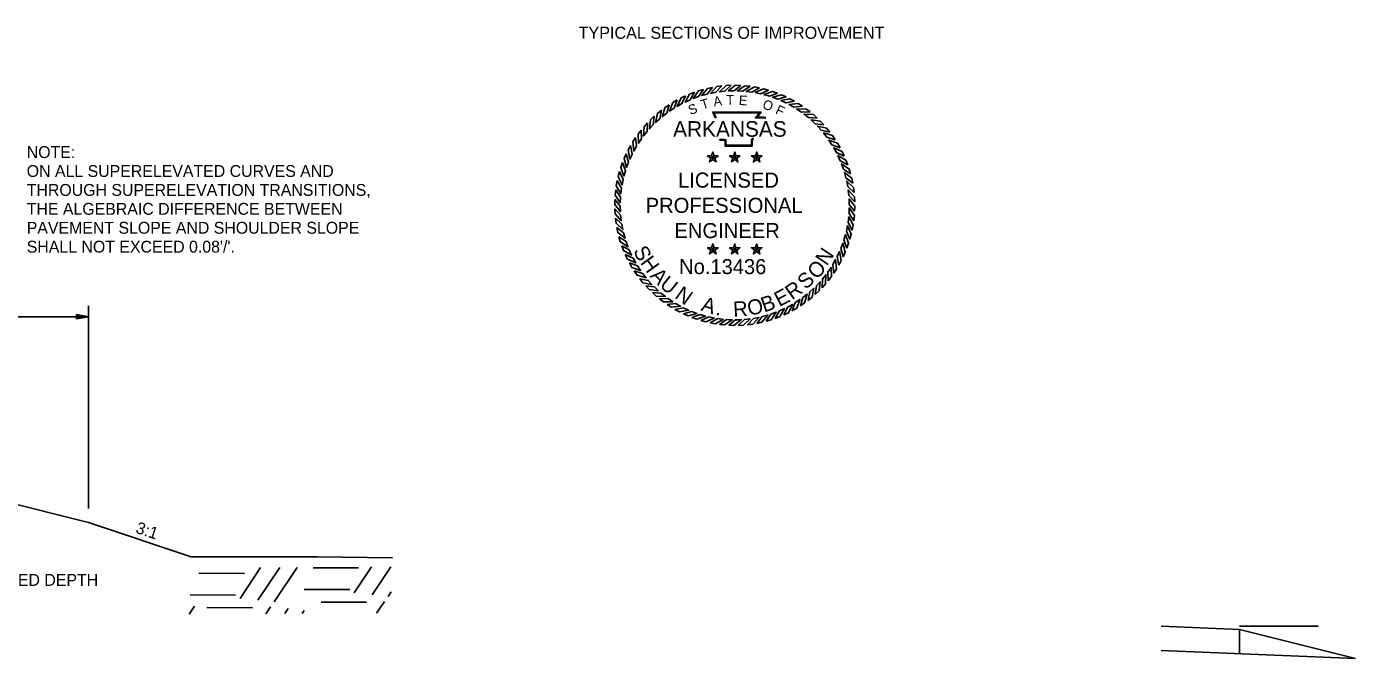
# Model space of a CAD drawing. Extents: x 1398183 to 1398373, y 1967240 to 1968889.
# Drawn here: x 1398293.8 to 1398359.8, y 1967459.6 to 1967491 of the extents above; entities that cross this region are included whole.
import ezdxf

# ---------------------------------------------------------------- set-up
doc = ezdxf.new("R2010")
doc.units = 0
for name, color, linetype in [('1', 7, 'Continuous'), ('10', 7, 'Continuous'), ('19', 7, 'Continuous'), ('42', 7, 'Continuous'), ('9', 7, 'Continuous'), ('G-ANNO-SYMB', 7, 'Continuous')]:
    doc.layers.add(name, color=color, linetype=linetype)

msp = doc.modelspace()

# ---------------------------------------------------------------- linework, layer by layer
at = {"layer": '19'}
for p, q in [((1398296.261, 1967476.707), (1398296.261, 1967476.497)), ((1398296.861, 1967476.602), (1398296.261, 1967476.707)), ((1398296.861, 1967467.07), (1398296.861, 1967477.148)), ((1398296.861, 1967476.602), (1398272.861, 1967476.602)), ((1398296.701, 1967476.617), (1398296.261, 1967476.652)), ((1398296.261, 1967476.497), (1398296.861, 1967476.602)), ((1398296.261, 1967476.547), (1398296.701, 1967476.587)), ((1398280.861, 1967470.374), (1398296.861, 1967466.374)), ((1398296.861, 1967466.374), (1398301.962, 1967464.674)), ((1398350.168, 1967461.218), (1398354.066, 1967461.062)), ((1398354.066, 1967461.062), (1398359.828, 1967459.621)), ((1398354.066, 1967461.062), (1398354.066, 1967459.852)), ((1398354.069, 1967461.218), (1398357.97, 1967461.218)), ((1398350.168, 1967460.008), (1398359.828, 1967459.621))]:
    msp.add_line(p, q, dxfattribs=at)
at = {"layer": '42'}
msp.add_lwpolyline([(1398301.962, 1967464.674), (1398308.248, 1967464.674), (1398311.963, 1967464.624)], dxfattribs=at)
at = {"layer": '9'}
for p, q in [((1398306.369, 1967464.141), (1398305.284, 1967462.514)), ((1398307.229, 1967464.146), (1398306.082, 1967462.426)), ((1398310.927, 1967464.167), (1398310.065, 1967462.875)), ((1398311.879, 1967464.172), (1398310.956, 1967462.787)), ((1398304.609, 1967463.846), (1398302.347, 1967463.852)), ((1398305.416, 1967464.136), (1398304.394, 1967462.602)), ((1398310.281, 1967464.119), (1398308.019, 1967464.125)), ((1398309.842, 1967463.041), (1398307.58, 1967463.046)), ((1398311.907, 1967462.93), (1398311.754, 1967462.699)), ((1398302.134, 1967462.218), (1398301.87, 1967461.822)), ((1398304.17, 1967462.768), (1398301.908, 1967462.774)), ((1398305.898, 1967462.184), (1398305.671, 1967461.843)), ((1398310.68, 1967462.415), (1398308.418, 1967462.42)), ((1398311.57, 1967462.457), (1398311.181, 1967461.874)), ((1398305.008, 1967462.142), (1398302.746, 1967462.148)), ((1398306.788, 1967462.096), (1398306.623, 1967461.849)), ((1398307.586, 1967462.008), (1398307.483, 1967461.853))]:
    msp.add_line(p, q, dxfattribs=at)
at = {"layer": 'G-ANNO-SYMB'}
for points in [[(1398327.879, 1967487.997), (1398327.628, 1967487.944), (1398327.343, 1967487.586), (1398327.61, 1967487.66)], [(1398328.342, 1967488.065), (1398328.088, 1967488.032), (1398327.776, 1967487.698), (1398328.048, 1967487.75)], [(1398328.81, 1967488.097), (1398328.553, 1967488.084), (1398328.216, 1967487.775), (1398328.492, 1967487.806)], [(1398329.278, 1967488.092), (1398329.021, 1967488.099), (1398328.661, 1967487.818), (1398328.938, 1967487.827)], [(1398329.745, 1967488.05), (1398329.489, 1967488.078), (1398329.108, 1967487.825), (1398329.385, 1967487.812)], [(1398330.206, 1967487.972), (1398329.954, 1967488.019), (1398329.554, 1967487.798), (1398329.829, 1967487.763)], [(1398330.661, 1967487.858), (1398330.413, 1967487.925), (1398329.997, 1967487.735), (1398330.268, 1967487.679)], [(1398326.121, 1967487.37), (1398325.898, 1967487.242), (1398325.738, 1967486.814), (1398325.97, 1967486.966)], [(1398326.54, 1967487.578), (1398326.309, 1967487.468), (1398326.115, 1967487.053), (1398326.358, 1967487.187)], [(1398326.975, 1967487.752), (1398326.735, 1967487.661), (1398326.51, 1967487.263), (1398326.763, 1967487.377)], [(1398327.422, 1967487.892), (1398327.176, 1967487.82), (1398326.92, 1967487.441), (1398327.181, 1967487.535)], [(1398331.105, 1967487.708), (1398330.863, 1967487.795), (1398330.433, 1967487.638), (1398330.699, 1967487.561)], [(1398331.535, 1967487.524), (1398331.301, 1967487.629), (1398330.861, 1967487.507), (1398331.12, 1967487.409)], [(1398331.951, 1967487.307), (1398331.725, 1967487.43), (1398331.277, 1967487.343), (1398331.527, 1967487.225)], [(1398325.337, 1967486.858), (1398325.137, 1967486.697), (1398325.046, 1967486.249), (1398325.251, 1967486.435)], [(1398325.719, 1967487.129), (1398325.507, 1967486.984), (1398325.381, 1967486.545), (1398325.6, 1967486.715)], [(1398332.347, 1967487.058), (1398332.132, 1967487.199), (1398331.678, 1967487.147), (1398331.919, 1967487.01)], [(1398332.723, 1967486.779), (1398332.52, 1967486.936), (1398332.063, 1967486.92), (1398332.292, 1967486.764)], [(1398333.076, 1967486.471), (1398332.886, 1967486.643), (1398332.429, 1967486.663), (1398332.646, 1967486.49)], [(1398324.643, 1967486.23), (1398324.471, 1967486.04), (1398324.451, 1967485.583), (1398324.624, 1967485.799)], [(1398324.977, 1967486.557), (1398324.791, 1967486.381), (1398324.735, 1967485.927), (1398324.925, 1967486.13)], [(1398333.404, 1967486.136), (1398333.228, 1967486.323), (1398332.774, 1967486.378), (1398332.976, 1967486.189)], [(1398333.704, 1967485.777), (1398333.543, 1967485.976), (1398333.095, 1967486.068), (1398333.282, 1967485.863)], [(1398324.055, 1967485.501), (1398323.915, 1967485.286), (1398323.967, 1967484.832), (1398324.104, 1967485.072)], [(1398324.335, 1967485.877), (1398324.178, 1967485.674), (1398324.194, 1967485.217), (1398324.35, 1967485.446)], [(1398333.976, 1967485.395), (1398333.831, 1967485.607), (1398333.391, 1967485.733), (1398333.561, 1967485.514)], [(1398334.216, 1967484.993), (1398334.088, 1967485.215), (1398333.66, 1967485.375), (1398333.812, 1967485.144)], [(1398323.589, 1967484.689), (1398323.484, 1967484.455), (1398323.606, 1967484.014), (1398323.704, 1967484.274)], [(1398323.806, 1967485.104), (1398323.683, 1967484.879), (1398323.771, 1967484.43), (1398323.888, 1967484.681)], [(1398327.889, 1967484.509), (1398327.95, 1967484.593), (1398327.889, 1967484.782), (1398327.828, 1967484.593)], [(1398328.98, 1967484.509), (1398329.041, 1967484.593), (1398328.98, 1967484.782), (1398328.919, 1967484.593)], [(1398330.071, 1967484.509), (1398330.132, 1967484.593), (1398330.071, 1967484.782), (1398330.01, 1967484.593)], [(1398334.424, 1967484.573), (1398334.314, 1967484.805), (1398333.9, 1967484.998), (1398334.034, 1967484.755)], [(1398323.405, 1967484.258), (1398323.319, 1967484.016), (1398323.475, 1967483.587), (1398323.553, 1967483.853)], [(1398327.889, 1967484.509), (1398327.828, 1967484.593), (1398327.63, 1967484.593), (1398327.79, 1967484.477)], [(1398327.889, 1967484.509), (1398327.79, 1967484.477), (1398327.729, 1967484.289), (1398327.889, 1967484.405)], [(1398327.889, 1967484.509), (1398327.988, 1967484.477), (1398328.148, 1967484.593), (1398327.95, 1967484.593)], [(1398327.889, 1967484.509), (1398327.889, 1967484.405), (1398328.049, 1967484.289), (1398327.988, 1967484.477)], [(1398328.98, 1967484.509), (1398328.919, 1967484.593), (1398328.721, 1967484.593), (1398328.881, 1967484.477)], [(1398328.98, 1967484.509), (1398328.881, 1967484.477), (1398328.82, 1967484.289), (1398328.98, 1967484.405)], [(1398328.98, 1967484.509), (1398329.079, 1967484.477), (1398329.239, 1967484.593), (1398329.041, 1967484.593)], [(1398328.98, 1967484.509), (1398328.98, 1967484.405), (1398329.14, 1967484.289), (1398329.079, 1967484.477)], [(1398330.071, 1967484.509), (1398330.01, 1967484.593), (1398329.812, 1967484.593), (1398329.972, 1967484.477)], [(1398330.071, 1967484.509), (1398329.972, 1967484.477), (1398329.911, 1967484.289), (1398330.071, 1967484.405)], [(1398330.071, 1967484.509), (1398330.17, 1967484.477), (1398330.33, 1967484.593), (1398330.132, 1967484.593)], [(1398330.071, 1967484.509), (1398330.071, 1967484.405), (1398330.231, 1967484.289), (1398330.17, 1967484.477)], [(1398334.599, 1967484.139), (1398334.508, 1967484.378), (1398334.11, 1967484.603), (1398334.224, 1967484.351)], [(1398334.739, 1967483.691), (1398334.667, 1967483.938), (1398334.288, 1967484.193), (1398334.382, 1967483.933)], [(1398323.141, 1967483.36), (1398323.094, 1967483.108), (1398323.316, 1967482.708), (1398323.35, 1967482.983)], [(1398323.256, 1967483.814), (1398323.189, 1967483.567), (1398323.378, 1967483.15), (1398323.434, 1967483.422)], [(1398334.843, 1967483.235), (1398334.791, 1967483.486), (1398334.433, 1967483.771), (1398334.506, 1967483.503)], [(1398334.912, 1967482.771), (1398334.879, 1967483.026), (1398334.544, 1967483.338), (1398334.596, 1967483.065)], [(1398323.063, 1967482.898), (1398323.036, 1967482.643), (1398323.288, 1967482.262), (1398323.301, 1967482.538)], [(1398334.944, 1967482.304), (1398334.931, 1967482.56), (1398334.622, 1967482.897), (1398334.652, 1967482.622)], [(1398323.022, 1967482.431), (1398323.014, 1967482.175), (1398323.296, 1967481.815), (1398323.287, 1967482.092)], [(1398334.897, 1967481.369), (1398334.924, 1967481.624), (1398334.672, 1967482.005), (1398334.659, 1967481.729)], [(1398334.939, 1967481.836), (1398334.946, 1967482.092), (1398334.664, 1967482.452), (1398334.673, 1967482.175)], [(1398323.017, 1967481.963), (1398323.029, 1967481.707), (1398323.338, 1967481.37), (1398323.308, 1967481.645)], [(1398323.048, 1967481.496), (1398323.081, 1967481.241), (1398323.416, 1967480.929), (1398323.364, 1967481.202)], [(1398334.819, 1967480.907), (1398334.866, 1967481.159), (1398334.644, 1967481.559), (1398334.61, 1967481.284)], [(1398323.117, 1967481.032), (1398323.169, 1967480.781), (1398323.527, 1967480.496), (1398323.454, 1967480.764)], [(1398334.555, 1967480.009), (1398334.641, 1967480.251), (1398334.485, 1967480.68), (1398334.407, 1967480.414)], [(1398334.704, 1967480.453), (1398334.771, 1967480.701), (1398334.582, 1967481.117), (1398334.526, 1967480.845)], [(1398323.221, 1967480.576), (1398323.293, 1967480.329), (1398323.672, 1967480.074), (1398323.579, 1967480.334)], [(1398323.361, 1967480.129), (1398323.452, 1967479.889), (1398323.85, 1967479.664), (1398323.736, 1967479.916)], [(1398327.889, 1967479.941), (1398327.828, 1967480.025), (1398327.63, 1967480.025), (1398327.79, 1967479.909)], [(1398327.889, 1967479.941), (1398327.95, 1967480.025), (1398327.889, 1967480.214), (1398327.828, 1967480.025)], [(1398327.889, 1967479.941), (1398327.988, 1967479.909), (1398328.148, 1967480.025), (1398327.95, 1967480.025)], [(1398328.98, 1967479.941), (1398328.919, 1967480.025), (1398328.721, 1967480.025), (1398328.881, 1967479.909)], [(1398328.98, 1967479.941), (1398329.041, 1967480.025), (1398328.98, 1967480.214), (1398328.919, 1967480.025)], [(1398328.98, 1967479.941), (1398329.079, 1967479.909), (1398329.239, 1967480.025), (1398329.041, 1967480.025)], [(1398330.071, 1967479.941), (1398330.01, 1967480.025), (1398329.812, 1967480.025), (1398329.972, 1967479.909)], [(1398330.071, 1967479.941), (1398330.132, 1967480.025), (1398330.071, 1967480.214), (1398330.01, 1967480.025)], [(1398330.071, 1967479.941), (1398330.17, 1967479.909), (1398330.33, 1967480.025), (1398330.132, 1967480.025)], [(1398334.371, 1967479.578), (1398334.476, 1967479.812), (1398334.354, 1967480.253), (1398334.256, 1967479.994)], [(1398323.536, 1967479.694), (1398323.646, 1967479.462), (1398324.06, 1967479.269), (1398323.926, 1967479.512)], [(1398327.889, 1967479.941), (1398327.79, 1967479.909), (1398327.729, 1967479.72), (1398327.889, 1967479.837)], [(1398327.889, 1967479.941), (1398327.889, 1967479.837), (1398328.049, 1967479.72), (1398327.988, 1967479.909)], [(1398328.98, 1967479.941), (1398328.881, 1967479.909), (1398328.82, 1967479.72), (1398328.98, 1967479.837)], [(1398328.98, 1967479.941), (1398328.98, 1967479.837), (1398329.14, 1967479.72), (1398329.079, 1967479.909)], [(1398330.071, 1967479.941), (1398329.972, 1967479.909), (1398329.911, 1967479.72), (1398330.071, 1967479.837)], [(1398330.071, 1967479.941), (1398330.071, 1967479.837), (1398330.231, 1967479.72), (1398330.17, 1967479.909)], [(1398333.905, 1967478.766), (1398334.045, 1967478.981), (1398333.993, 1967479.435), (1398333.856, 1967479.195)], [(1398334.154, 1967479.163), (1398334.277, 1967479.388), (1398334.19, 1967479.837), (1398334.072, 1967479.586)], [(1398323.744, 1967479.274), (1398323.872, 1967479.052), (1398324.3, 1967478.892), (1398324.148, 1967479.123)], [(1398323.984, 1967478.872), (1398324.129, 1967478.66), (1398324.569, 1967478.534), (1398324.399, 1967478.753)], [(1398333.317, 1967478.037), (1398333.49, 1967478.228), (1398333.509, 1967478.684), (1398333.336, 1967478.468)], [(1398333.625, 1967478.39), (1398333.782, 1967478.593), (1398333.766, 1967479.05), (1398333.61, 1967478.821)], [(1398324.256, 1967478.49), (1398324.417, 1967478.291), (1398324.865, 1967478.199), (1398324.678, 1967478.404)], [(1398324.556, 1967478.131), (1398324.732, 1967477.944), (1398325.186, 1967477.889), (1398324.984, 1967478.078)], [(1398332.623, 1967477.409), (1398332.823, 1967477.57), (1398332.914, 1967478.018), (1398332.709, 1967477.832)], [(1398332.983, 1967477.71), (1398333.169, 1967477.886), (1398333.225, 1967478.34), (1398333.035, 1967478.138)], [(1398324.884, 1967477.796), (1398325.074, 1967477.624), (1398325.531, 1967477.604), (1398325.314, 1967477.777)], [(1398325.237, 1967477.488), (1398325.44, 1967477.331), (1398325.897, 1967477.347), (1398325.668, 1967477.503)], [(1398331.839, 1967476.897), (1398332.062, 1967477.025), (1398332.222, 1967477.453), (1398331.99, 1967477.301)], [(1398332.241, 1967477.138), (1398332.453, 1967477.283), (1398332.579, 1967477.722), (1398332.36, 1967477.552)], [(1398325.613, 1967477.209), (1398325.828, 1967477.069), (1398326.282, 1967477.12), (1398326.041, 1967477.258)], [(1398326.009, 1967476.96), (1398326.235, 1967476.837), (1398326.684, 1967476.924), (1398326.433, 1967477.042)], [(1398326.425, 1967476.743), (1398326.659, 1967476.638), (1398327.099, 1967476.76), (1398326.84, 1967476.858)], [(1398326.855, 1967476.559), (1398327.097, 1967476.473), (1398327.527, 1967476.629), (1398327.261, 1967476.706)], [(1398330.538, 1967476.375), (1398330.784, 1967476.447), (1398331.04, 1967476.826), (1398330.779, 1967476.732)], [(1398330.985, 1967476.515), (1398331.225, 1967476.606), (1398331.45, 1967477.004), (1398331.197, 1967476.89)], [(1398331.42, 1967476.689), (1398331.651, 1967476.799), (1398331.845, 1967477.214), (1398331.602, 1967477.08)], [(1398327.299, 1967476.409), (1398327.547, 1967476.342), (1398327.963, 1967476.532), (1398327.692, 1967476.588)], [(1398327.754, 1967476.295), (1398328.006, 1967476.248), (1398328.406, 1967476.469), (1398328.131, 1967476.504)], [(1398328.216, 1967476.217), (1398328.471, 1967476.189), (1398328.852, 1967476.442), (1398328.575, 1967476.455)], [(1398328.682, 1967476.175), (1398328.939, 1967476.168), (1398329.299, 1967476.449), (1398329.022, 1967476.44)], [(1398329.151, 1967476.17), (1398329.407, 1967476.183), (1398329.744, 1967476.492), (1398329.468, 1967476.461)], [(1398329.618, 1967476.202), (1398329.872, 1967476.235), (1398330.184, 1967476.569), (1398329.912, 1967476.517)], [(1398330.081, 1967476.27), (1398330.332, 1967476.323), (1398330.617, 1967476.681), (1398330.35, 1967476.608)]]:
    msp.add_lwpolyline(points, close=True, dxfattribs=at)
for points in [[(1398328.024, 1967486.464), (1398327.885, 1967486.765), (1398330.292, 1967486.766), (1398330.09, 1967486.513), (1398330.254, 1967486.516), (1398330.391, 1967486.517), (1398330.527, 1967486.503)], [(1398328.059, 1967486.479), (1398327.945, 1967486.727), (1398330.212, 1967486.728), (1398330.011, 1967486.474), (1398330.254, 1967486.478), (1398330.389, 1967486.479), (1398330.523, 1967486.465)], [(1398329.912, 1967485.455), (1398329.871, 1967485.422), (1398329.858, 1967485.372), (1398329.844, 1967485.247), (1398329.844, 1967485.081), (1398328.501, 1967485.081), (1398328.501, 1967485.305), (1398328.501, 1967485.355), (1398328.446, 1967485.372), (1398328.255, 1967485.372), (1398328.221, 1967485.424)], [(1398329.888, 1967485.485), (1398329.838, 1967485.444), (1398329.82, 1967485.379), (1398329.806, 1967485.249), (1398329.806, 1967485.119), (1398328.539, 1967485.119), (1398328.539, 1967485.305), (1398328.539, 1967485.383), (1398328.452, 1967485.41), (1398328.276, 1967485.41), (1398328.253, 1967485.444)]]:
    msp.add_lwpolyline(points, dxfattribs=at)

# ---------------------------------------------------------------- texts
at = {"layer": '1'}
msp.add_text('TYPICAL SECTIONS OF IMPROVEMENT', height=0.6, dxfattribs=at).set_placement((1398321.219, 1967490.407))
at = {"layer": '10'}
msp.add_text('3:1', height=0.59, rotation=341.58682, dxfattribs=at).set_placement((1398299.165, 1967465.871))
at = {"layer": '19'}
for s, height, p in [('NOTE:', 0.59, (1398293.791, 1967484.484)), ('ON ALL SUPERELEVATED CURVES AND', 0.59001, (1398293.791, 1967483.544)), ('THROUGH SUPERELEVATION TRANSITIONS,', 0.59001, (1398293.791, 1967482.604)), ('THE ALGEBRAIC DIFFERENCE BETWEEN', 0.59001, (1398293.791, 1967481.664)), ('PAVEMENT SLOPE AND SHOULDER SLOPE', 0.59001, (1398293.791, 1967480.724)), ("SHALL NOT EXCEED 0.08'/'.", 0.59001, (1398293.791, 1967479.784))]:
    msp.add_text(s, height=height, dxfattribs=at).set_placement(p)
msp.add_text('(CLASS 7) - VAR. COMPACTED DEPTH', height=0.59001, rotation=360, dxfattribs=at).set_placement((1398282.874, 1967463.226))
at = {"layer": 'G-ANNO-SYMB'}
for s, height, rotation, p in [('T', 0.475, 16.90148, (1398327.375, 1967486.892)), ('A', 0.475, 8.67877, (1398327.951, 1967487.043)), ('T', 0.475, 1.47887, (1398328.564, 1967487.137)), ('E', 0.475, 356.67203, (1398329.171, 1967487.123)), ('O', 0.475, 341.2218, (1398330.324, 1967486.96)), ('S', 0.475, 19.77256, (1398326.771, 1967486.621)), ('F', 0.475, 335.36282, (1398330.964, 1967486.71)), ('S', 0.75, 298.16364, (1398323.912, 1967479.874)), ('N', 0.75, 56.10067, (1398333.554, 1967479.09)), ('H', 0.75, 305.61905, (1398324.254, 1967479.286)), ('O', 0.75, 44.77573, (1398333.033, 1967478.415)), ('A', 0.75, 313.44722, (1398324.73, 1967478.601)), ('S', 0.75, 43.48784, (1398332.518, 1967477.917)), ('U', 0.75, 320.90262, (1398325.198, 1967478.112)), ('N', 0.75, 324.93262, (1398325.954, 1967477.554)), ('E', 0.75, 27.83149, (1398331.194, 1967477.075)), ('R', 0.75, 35.65967, (1398331.828, 1967477.408)), ('A', 0.75, 343.09908, (1398327.261, 1967476.91)), ('R', 0.75, 3.22866, (1398328.918, 1967476.597)), ('O', 0.75, 11.42961, (1398329.685, 1967476.645)), ('B', 0.75, 18.88501, (1398330.437, 1967476.804)), ('.', 0.75, 351.30002, (1398327.998, 1967476.692))]:
    msp.add_text(s, height=height, rotation=rotation, dxfattribs=at).set_placement(p)
for s, height, p in [('ARKANSAS', 0.7747, (1398325.918, 1967485.542)), ('LICENSED', 0.75, (1398326.159, 1967483.013)), ('PROFESSIONAL', 0.75, (1398324.551, 1967481.759)), ('ENGINEER', 0.75, (1398325.98, 1967480.504)), ('No.13436', 0.747, (1398326.217, 1967478.716))]:
    msp.add_text(s, height=height, dxfattribs=at).set_placement(p)

doc.saveas('drawing.dxf')
